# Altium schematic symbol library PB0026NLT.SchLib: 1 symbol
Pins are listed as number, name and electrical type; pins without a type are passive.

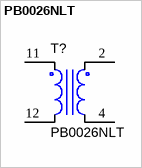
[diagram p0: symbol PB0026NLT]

## PB0026NLT
designator T?
XFRMR CURR SENSE 5.6MH 100:1 SMD; Manufacturer: Pulse Engineering; CompType: Transformer; Ns1toNp: 1:100; Rp: .42 mOhm; Rs1: .700 Ohm; SymbolVersion: 2012 - 11 - 07; U/M: EA
footprint PBXXXX (PULSE PBXXXX TRANSFORMER)
pins: 2, 4, 11, 12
